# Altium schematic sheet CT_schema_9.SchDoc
size 318 x 188 mm
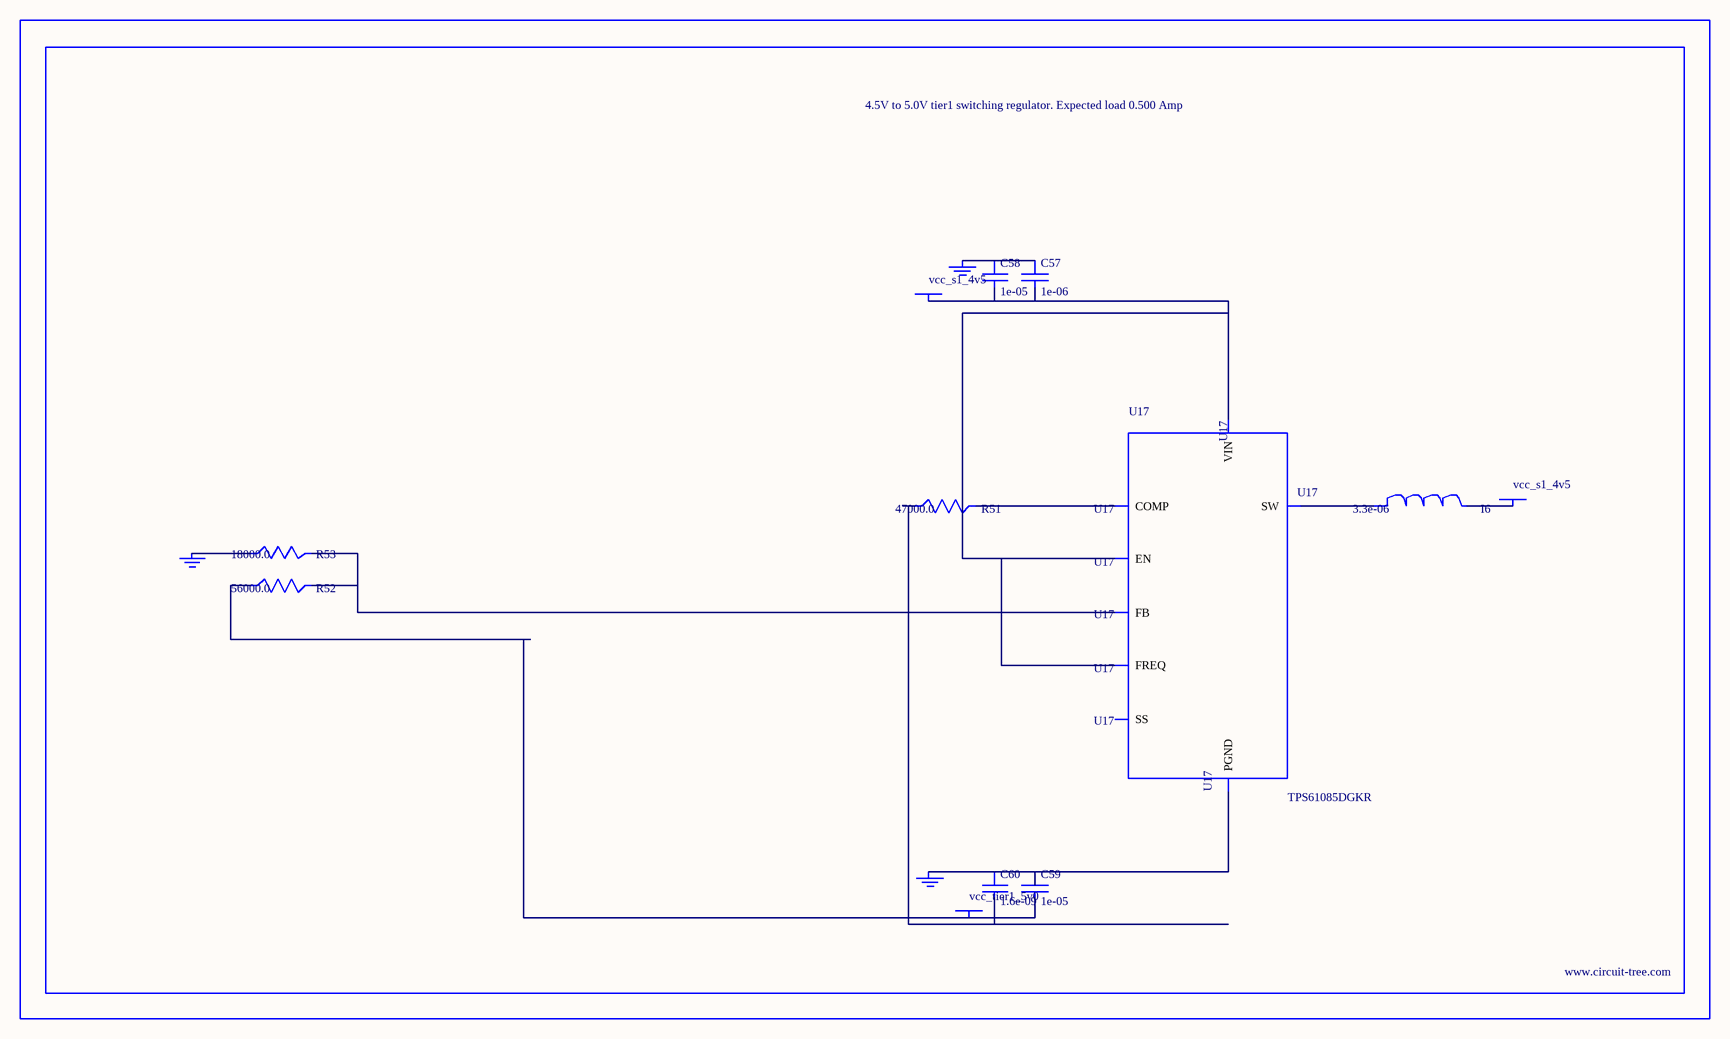
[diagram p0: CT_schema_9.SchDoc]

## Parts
BORDER8  (no value)
C57  1e-06  [C0603]
C58  1e-05  [C0805]
C59  1e-05  [C0805]
C60  1.6e-09  [C0603]
GND_INSTANCE_8_0  (no value)
GND_INSTANCE_8_1  (no value)
GND_INSTANCE_8_2  (no value)
I6  3.3e-06  [L0806]
POWER_INSTANCE_8_0  vcc_tier1_5v0
POWER_INSTANCE_8_1  vcc_s1_4v5
POWER_INSTANCE_8_2  vcc_s1_4v5
R51  47000.0  [R0603]
R52  56000.0  [R0603]
R53  18000.0  [R0603]
U17  TPS61085DGKR  [MSOP-8]

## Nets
NetC57_1: C57.1 C58.1 GND_INSTANCE_8_2.0(GND)
NetC57_2: C57.2 C58.2 POWER_INSTANCE_8_2.0(PWR) U17.3(EN) U17.6(VIN) U17.7(FREQ)
NetC59_1: C59.1 C60.1 GND_INSTANCE_8_1.0(GND) U17.4(PGND)
NetC59_2: C59.2 POWER_INSTANCE_8_0.0(PWR) R52.1
NetC60_2: C60.2 R51.1
NetGND_INSTANCE_8_0_0: GND_INSTANCE_8_0.0(GND) R53.1
NetI6_1: I6.1 U17.5(SW)
NetI6_2: I6.2 POWER_INSTANCE_8_1.0(PWR)
NetR51_2: R51.2 U17.1(COMP)
NetR52_2: R52.2 R53.2 U17.2(FB)

Not connected (* = marked no-connect by the designer): U17 8(SS)

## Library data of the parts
BORDER8 = BORDER_PAGE8
C57 = C0603C105K3RACTU
C58 C59 = C0805C106K8RACTU
C60 = 06035C162JAT2A
GND_INSTANCE_8_0-GND_INSTANCE_8_2 = GND
I6 = L0806C3R3MDWIT
POWER_INSTANCE_8_0-POWER_INSTANCE_8_2 = PWR
R51 = RC0603JR-0747KL
R52 = RC0603JR-0756KL
R53 = RC0603JR-0718KL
